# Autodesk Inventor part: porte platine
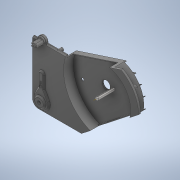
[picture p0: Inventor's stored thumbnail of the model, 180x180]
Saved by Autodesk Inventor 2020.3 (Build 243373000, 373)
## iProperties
Created: 2020-09
Part Number: porte platine
Material: Plastique ABS
Document SubType Name: Modeling
Designer: ficho
Density: 1.06 g/cm^3
Appearance: Lisse - Noir
Mass: 156.331 g
Surface Area: 1026.77 cm^2
Volume: 147.482 cm^3
Author: ficho
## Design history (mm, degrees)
sketch "Esquisse1"
  geometry: L1 (0, 0)-(123, 0); L2 (0, 150)-(0, 0) reference; L3 (123, 0)-(266.132, 112.432); L4 (123, 0)-(298, 0); L5 (81.513, 142)-(222.171, 188.034); L6 (84, 150)-(0, 150) reference; C1 r 3.5 at (178.4, 112); C2 r 3 at (101, 94); C3 r 10 at (160.2, 111.986); A1 r 104.643 centre (182.601, 114.958) between (84, 150) and (145.019, 17.296); A2 r 68 centre (178.4, 112) between (244.316, 95.295) and (192.867, 178.443); A3 r 87.733 centre (178.4, 112) between (266.132, 112.432) and (222.171, 188.034); A4 r 22.5 centre (101, 94) between (84.399, 78.813) and (79.135, 99.308); 1 further point
  constraints: 12 end point, 12 point on circle, 7 centre point, 3 coincident, 3 horizontal, 3 point on line, 1 parallel, 1 vertical
  dimensions: "d3" = 38.15 deg angle of L4 L3; "d6" = 28 distance of A1.end L1.end; "d7" = 78 distance from line of point (78, 112) L2; "d9" = 84 distance from line of L6.start L2; "d10" = 148 distance of L5.end L5.start; "d11" = 161.878 deg angle of L5 L6; "d14" = 30.83438 distance of L5.end A2.end; "d15" = 7 diameter of C1; "d18" = 6 diameter of C2; "d19" = 45 diameter of A4; "d20" = 20 diameter of C3; "d21" = 43 distance edge to line of C3 L5
extrude "Extrusion1" new body sketch "Esquisse1" distance "d23" = 33; taper "d24" = 0 deg
sketch "Esquisse2"
  geometry: L1 (123, 0)-(266.132, 112.432) reference; L2 (222.171, 188.034)-(81.513, 142) reference; A1 r 68 centre (178.4, 112) between (244.316, 95.295) and (192.867, 178.443) reference; A2 r 104.643 centre (182.601, 114.958) between (84, 150) and (145.019, 17.296) reference; 1 further point
extrude "Extrusion2" cut sketch "Esquisse2" distance "d25" = 21; taper "d26" = 0 deg
sketch "Esquisse3"
  geometry: L1 (244.316, 95.295)-(145.019, 17.296) reference; L2 (81.513, 142)-(192.867, 178.443) reference; L3 (142.869, 18.151)-(245.025, 98.395); L4 (244.316, 95.295)-(145.019, 17.296) reference; L5 (80.926, 139.704)-(196.531, 177.538); L6 (81.513, 142)-(192.867, 178.443) reference; C1 r 3 at (101, 94) reference; C2 r 10 at (160.2, 111.986) reference; A1 r 104.643 centre (182.601, 114.958) between (81.513, 142) and (145.019, 17.296) reference; A2 r 68 centre (178.4, 112) between (244.316, 95.295) and (192.867, 178.443) reference; 1 further point
  constraints: 4 end point, 4 point on circle, 2 parallel
  dimensions: "d27" = 2 distance between parallel lines of L1 L3; "d28" = 2 distance between parallel lines of L2 L5 (= d27)
extrude "Extrusion3" cut sketch "Esquisse3" distance "d29" = 4; taper "d30" = 0 deg
extrude "Extrusion4" join sketch "Esquisse1" distance "d31" = 52; taper "d32" = 0 deg
fillet "Congé1" dims "d33" = 3.5
node "Plan de construction1"
  node "Axe de construction1"
sketch "Esquisse5"
  geometry: L1 (28, 73)-(-11.719, 73); L2 (-11.719, 73)-(-11.719, 113.106); L3 (-11.719, 113.106)-(28, 113.106); L4 (28, 113.106)-(28, 73); L5 (33, 44.145)-(33, 87.733) reference; L6 (33, 68)-(8, 68) reference; L7 (-24.463, 0)-(64.744, 0) reference; 1 further point
  constraints: 8 end point, 2 parallel, 1 horizontal, 1 perpendicular
  dimensions: "d36" = 5 distance between parallel lines of L4 L5; "d37" = 5 distance between parallel lines of L1 L6 (= d36)
revolve "Révolution1" sketch "Esquisse5" stored, may be unused: angle "d38" = 180 deg
sketch "Esquisse6"
  geometry: L1 (28, -260.408)-(-21.682, -260.408); L2 (-21.682, -260.408)-(-21.682, -105.427); L3 (-21.682, -105.427)-(28, -105.427); L4 (28, -105.427)-(28, -260.408); L5 (33, -94.212)-(33, -178.211) reference; L6 (33, -100.427)-(8, -100.427) reference; L7 (-36.418, 0)-(66.736, 0) reference; 1 further point
  constraints: 8 end point, 2 parallel, 1 horizontal, 1 perpendicular
  dimensions: "d39" = 5 distance between parallel lines of L4 L5; "d40" = 5 distance between parallel lines of L6 L3 (= d39)
revolve "Révolution2" sketch "Esquisse6" stored, may be unused: angle "d41" = 150 deg
fillet "Congé2" dims "d42" = 15
sketch "Esquisse7"
  geometry: L1 (80.059, 0)-(80.059, -135) reference; L2 (0, 0)-(80.059, 0) reference; L3 (-42.941, -150)-(-60.333, -136.338) reference; L4 (65.059, -150)-(-42.941, -150) reference; L5 (-170.363, -49.909)-(-186.073, -37.568) reference; L6 (-142.112, 38.034)-(-121.41, 31.259) reference; L7 (-183.053, -36.125)-(-170.94, -45.641); L8 (-125.936, 29.583)-(-141.761, 34.763); L9 (65.059, -147)-(-41.903, -147); L10 (-41.903, -147)-(-57.13, -135.039); L11 (1.107, -3)-(77.059, -3); L12 (77.059, -3)-(77.059, -135); A1 r 15 centre (65.059, -135) between (65.059, -150) and (80.059, -135) reference; A2 r 105.427 centre (-98.341, -38) between (-60.333, -136.338) and (0, 0) reference; A3 r 73 centre (-98.341, -38) between (-121.41, 31.259) and (-170.363, -49.909) reference; A4 r 87.733 centre (-98.341, -38) between (-142.112, 38.034) and (-186.073, -37.568) reference; A5 r 84.733 centre (-98.341, -38) between (-141.761, 34.763) and (-183.053, -36.125); A6 r 12 centre (65.059, -135) between (65.059, -147) and (77.059, -135); A7 r 105.427 centre (-98.341, -38) between (-60.333, -136.338) and (0, 0) reference; A8 r 73 centre (-98.341, -38) between (-121.41, 31.259) and (-170.363, -49.909) reference; 1 further point
  constraints: 12 end point, 8 point on circle, 2 centre point, 1 other
  dimensions: "d43" = 3 distance between parallel lines of L5 L7; "d44" = 3 radial gap between concentric circles of A1 A6
extrude "Extrusion5" cut sketch "Esquisse7" distance "d45" = 3; taper "d46" = 0 deg
sketch "Esquisse8"
  geometry: L1 (-84, 150)-(-80.059, 150) reference; L2 (-201.47, 181.259)-(-81.513, 142) reference; L3 (-140.393, 13.662)-(-250.422, 100.091) reference; L4 (-81.513, 142)-(-76.895, 140.489); L5 (-84, 150)-(-80.059, 150) reference; C1 r 10 at (-160.2, 111.986) reference; C2 r 3 at (-101, 94) reference; A1 r 105.427 centre (-178.4, 112) between (-140.393, 13.662) and (-80.059, 150) reference; A2 r 104.643 centre (-182.601, 114.958) between (-81.513, 142) and (-84, 150) reference; A3 r 73 centre (-178.4, 112) between (-201.47, 181.259) and (-250.422, 100.091) reference; A4 r 104.643 centre (-182.601, 114.958) between (-80.926, 139.704) and (-81.513, 142) reference; A5 r 105.427 centre (-178.4, 112) between (-140.393, 13.662) and (-80.059, 150) reference; A6 r 104.643 centre (-182.601, 114.958) between (-145.019, 17.296) and (-84, 150) reference; 2 further points
  constraints: 2 end point, 1 point on circle
extrude "Extrusion6" cut sketch "Esquisse8" stored distance "d47" = 10; taper "d48" = 0 deg
sketch "Esquisse9"
  geometry: L1 (-201.47, 181.259)-(-76.895, 140.489) reference; L2 (-140.393, 13.662)-(-250.422, 100.091) reference; L3 (-203.033, 180.718)-(-187.21, 175.54); L4 (-186.221, 175.244)-(-76.561, 139.273); L5 (-139.329, 14.08)-(-236.917, 90.736); L6 (-237.702, 91.371)-(-250.647, 101.539); L7 (-213.165, 132.272)-(-241.256, 149.124); L8 (-212.651, 133.13)-(-240.741, 149.981); L9 (-245.025, 98.395)-(-142.869, 18.151) reference; L10 (-119.045, 24.869)-(-226.02, 108.899); L11 (-226.813, 109.522)-(-249.73, 127.524); L12 (-236.917, 90.736)-(-226.02, 108.899); L13 (-118.182, 25.463)-(-225.502, 109.764); L14 (-226.295, 110.386)-(-249.487, 128.604); L15 (-237.702, 91.371)-(-226.813, 109.522); L16 (-226.295, 110.386)-(-213.165, 132.272); L17 (-226.96, 166.506)-(-198.274, 157.096); L18 (-197.299, 156.776)-(-73.049, 116.02); L19 (-225.502, 109.764)-(-197.299, 156.776); L20 (-196.772, 157.656)-(-186.221, 175.244); L21 (-212.651, 133.13)-(-198.274, 157.096); L22 (-197.746, 157.976)-(-187.21, 175.54); L23 (-226.087, 167.272)-(-197.746, 157.976); L24 (-196.772, 157.656)-(-73.096, 117.087); C1 r 3 at (-101, 94) reference; C2 r 10 at (-160.2, 111.986) reference; C3 r 3.5 at (-178.4, 112) reference; A1 r 73 centre (-178.4, 112) between (-201.47, 181.259) and (-250.422, 100.091) reference; A2 r 105.427 centre (-178.4, 112) between (-140.393, 13.662) and (-76.895, 140.489) reference; 8 further points
  constraints: 42 end point, 25 parallel, 8 point on circle, 7 other
extrude "Extrusion7" cut sketch "Esquisse9" distance "d59" = 5; taper "d60" = 0 deg
sketch "Esquisse10"
  geometry: L1 (80.059, 0)-(80.059, -135) reference; L2 (65.059, -150)-(-42.941, -150) reference; C1 r 6 at (55.059, -127.5); 1 further point
  constraints: 1 centre point
  dimensions: "d61" = 25 distance from line of C1.centre L1; "d62" = 22.5 distance from line of L2 C1.centre; "d63" = 12 diameter of C1
extrude "Extrusion8" join sketch "Esquisse10" distance "d64" = 16; taper "d65" = 0 deg
sketch "Esquisse11"
  geometry: C1 r 6 at (0, 0) reference; 2 further points
  constraints: 1 coincident
hole "Perçage1" sketch "Esquisse11" at (0, 0) diameter "d66" = 8; stored, may be unused: countersink angle "d70" = 90 deg, drill point angle "d72" = 118 deg; dims "d67" = 6, "d68" = 4, "d69" = 2, "d71" = 8
sketch "Esquisse12"
  geometry: C1 r 4 at (25, 22.5) reference; C2 r 13.5 at (25, 22.5); 1 further point
  constraints: 1 centre point, 1 coincident
  dimensions: "d73" = 27 diameter of C2
extrude "Extrusion9" join sketch "Esquisse12" distance "d74" = 8.5; taper "d75" = 0 deg
sketch "Esquisse13" dims "d76" = 40, "d79" = 15
  geometry: L1 (15, 0)-(123, 0) reference; L2 (32.395, 81.5)-(17.395, 81.5); L3 (17.395, 81.5)-(17.395, 50.391); L4 (32.395, 50.706)-(32.395, 81.5); L5 (25, 22.5)-(25, 55.638); C1 r 13.5 at (25, 22.5) reference; A1 r 120.352 centre (117.494, -16.426) between (17.395, 50.391) and (6.566, 30.258); A2 r 120.352 centre (-67.494, -16.426) between (43.434, 30.258) and (32.395, 50.706); 5 further points
  constraints: 8 end point, 5 point on circle, 3 symmetric about line, 2 centre point, 1 coincident, 1 horizontal, 1 parallel, 1 perpendicular, 1 vertical, 8 other
  dimensions: "d80" = 89 dimension on L1
extrude "Extrusion10" join sketch "Esquisse13" distance "d81" = 4; taper "d82" = 0 deg
chamfer "Chanfrein1" distance "d83" = 3; stored, may be unused: second distance "d84" = 2, angle "d85" = 50 deg
chamfer "Chanfrein2" distance "d86" = 3; stored, may be unused: second distance "d87" = 2, angle "d88" = 50 deg
sketch "Esquisse14"
  geometry: C1 r 3 at (25, 55.5); C2 r 4 at (25, 22.5) reference; 1 further point
  constraints: 1 centre point
  dimensions: "d89" = 6 diameter of C1; "d90" = 26 dimension on C2 C1
extrude "Extrusion11" cut sketch "Esquisse14" extent not by distance; stored distance "d91" = 15; taper "d92" = 0 deg
sketch "Esquisse15"
  geometry: L1 (25, 59.5)-(23.75, 59.5); L2 (23.75, 59.5)-(23.75, 67); L3 (23.75, 67)-(25, 67); L4 (25, 67)-(25, 59.5); L5 (25, 59.5)-(26.25, 59.5); L6 (26.25, 59.5)-(26.25, 67); L7 (26.25, 67)-(25, 67); L8 (25, 67)-(25, 59.5); C1 r 3 at (25, 55.5) reference; C2 r 4 at (25, 55.5); 2 further points
  constraints: 16 end point, 4 parallel, 2 horizontal, 2 perpendicular, 1 centre point, 1 tangent
  dimensions: "d93" = 1 radial gap between concentric circles of C1 C2; "d94" = 1.25 distance of L2.end L3.end; "d95" = 7.5 distance of L1.end L2.end; "d97" = 1.25 distance of L7.end L6.end
extrude "Extrusion12" cut sketch "Esquisse15" extent not by distance; stored distance "d98" = 15; taper "d99" = 0 deg
sketch "Esquisse16"
  geometry: L1 (0, 150)-(0, 15) reference; L2 (84, 150)-(0, 150) reference; L3 (34, 153)-(34, 150); L4 (14, 153)-(14, 150); A1 r 10 centre (24, 153) between (34, 153) and (14, 153); 1 further point
  constraints: 4 end point, 2 perpendicular, 2 point on circle, 2 point on line, 2 tangent, 1 centre point
  dimensions: "d100" = 20 diameter of A1; "d101" = 24 distance from line of L1 A1.centre; "d102" = 13 dimension on A1 L2
extrude "Extrusion13" join sketch "Esquisse16" stored distance "d103" = 3; taper "d104" = 0 deg
sketch "Esquisse17"
  geometry: C1 r 9 at (24, 153); A1 r 10 centre (24, 153) between (34, 153) and (14, 153) reference; 1 further point
  constraints: 1 centre point, 1 coincident
  dimensions: "d105" = 18 diameter of C1
extrude "Extrusion14" join sketch "Esquisse17" distance "d106" = 3; taper "d107" = 0 deg
chamfer "Chanfrein3" distance "d108" = 3; stored, may be unused: second distance "d109" = 2, angle "d110" = 15 deg
sketch "Esquisse18"
  geometry: L1 (3.25, 4)-(-4.25, 4); L2 (-4.25, 4)-(-4.25, -4); L3 (-4.25, -4)-(3.25, -4); C1 r 8.196 at (0, 0) reference; A1 r 4 centre (3.25, 0) between (3.25, -4) and (3.25, 4); 1 further point
  constraints: 6 end point, 2 point on circle, 1 centre point, 1 horizontal, 1 parallel, 1 perpendicular, 1 tangent
  dimensions: "d111" = 8 distance between parallel lines of L3 L1; "d112" = 4 distance from line of C1.centre L1 (= 0.5 x d111); "d114" = 11.5 dimension on A1 L2
extrude "Extrusion15" join sketch "Esquisse18" distance "d115" = 17; taper "d116" = 0 deg
sketch "Esquisse19"
  geometry: L1 (-4.25, 4)-(-4.25, -4) reference; L2 (-4.25, 1.5)-(1.75, 1.5); L3 (1.75, 1.5)-(1.75, -1.5); L4 (1.75, -1.5)-(-4.25, -1.5); L5 (-4.25, -1.5)-(-4.25, 1.5); 2 further points
  constraints: 8 end point, 2 parallel, 1 horizontal, 1 perpendicular, 1 point on line
  dimensions: "d117" = 3 distance between parallel lines of L4 L2; "d118" = 6 distance between parallel lines of L1 L3; "d119" = 2.5 distance from line of L2 L1.start; "d120" = 2.5 distance of L4.end L1.end (derived)
extrude "Extrusion16" cut sketch "Esquisse19" extent not by distance; stored distance "d121" = 0; taper "d122" = 0 deg
sketch "Esquisse20"
  geometry: L1 (103.25, 157)-(103.25, 154.5) reference; L2 (103.25, 151.5)-(103.25, 149) reference; L3 (103.25, 157)-(100.25, 157); L4 (100.25, 157)-(100.25, 149); L5 (100.25, 149)-(103.25, 149); L6 (103.25, 149)-(103.25, 157); L7 (100.25, 155)-(93, 155); L8 (93, 155)-(93, 151); L9 (93, 151)-(100.25, 151); L10 (100.25, 151)-(100.25, 155); L11 (103.25, 151.5)-(97.25, 151.5) reference; A1 r 10 centre (99, 153) between (109, 153) and (89, 153) reference; 5 further points
  constraints: 16 end point, 4 parallel, 2 horizontal, 2 perpendicular, 1 point on line
  dimensions: "d123" = 3 distance of L5.end L4.end; "d124" = 4 distance between parallel lines of L9 L7; "d125" = 0.5 distance between parallel lines of L9 L11; "d126" = 4 distance edge to line of A1 L8
extrude "Extrusion17" cut sketch "Esquisse20" distance "d127" = 12; taper "d128" = 0 deg
sketch "Esquisse21"
  geometry: L1 (103.25, 157)-(103.25, 154.5) reference; L2 (100.25, 155)-(100.25, 157) reference; L3 (103.25, 157)-(100.25, 157); L4 (100.25, 157)-(100.25, 156.5); L5 (100.25, 156.5)-(103.25, 156.5); L6 (103.25, 156.5)-(103.25, 157); 3 further points
  constraints: 8 end point, 2 parallel, 1 horizontal, 1 perpendicular, 1 point on line
  dimensions: "d129" = 0.5 distance of L4.end L3.end
extrude "Extrusion18" join sketch "Esquisse21" stored distance "d130" = 10; taper "d131" = 0 deg
sketch "Esquisse22"
  geometry: L1 (-4.25, -4)-(-1.25, -4) reference; L2 (1.75, -1.5)-(-4.25, -1.5) reference; L3 (-4.25, -4)-(-1.75, -4); L4 (-1.75, -4)-(-1.75, -1.5); L5 (-1.75, -1.5)-(-4.25, -1.5); L6 (-4.25, -1.5)-(-4.25, -4); L7 (-4.25, 4)-(3.25, 4) reference; L8 (-4.25, 1.5)-(1.75, 1.5) reference; L9 (-4.25, 4)-(-1.75, 4); L10 (-1.75, 4)-(-1.75, 1.5); L11 (-1.75, 1.5)-(-4.25, 1.5); L12 (-4.25, 1.5)-(-4.25, 4); L13 (4.75, 1.5)-(6.958, 1.5); L14 (6.958, -1.5)-(4.75, -1.5); L15 (4.75, -1.5)-(4.75, 1.5); L16 (1.75, -1.5)-(-4.25, -1.5) reference; A1 r 4 centre (3.25, 0) between (3.25, -4) and (3.25, 4) reference; 5 further points
  constraints: 22 end point, 5 parallel, 3 horizontal, 3 point on line, 2 perpendicular, 2 point on circle, 1 collinear
  dimensions: "d132" = 2.5 distance of L5.end L4.end; "d133" = 3 distance between parallel lines of L14 L13; "d134" = 2.5 distance edge to line of A1 L15
extrude "Extrusion19" join sketch "Esquisse22" distance "d135" = 2; taper "d136" = 0 deg
chamfer "Chanfrein4" distance "d137" = 3; stored, may be unused: second distance "d138" = 2, angle "d139" = 15 deg
sketch "Esquisse23"
  geometry: L1 (60.087, -101.804)-(60.087, -127.5) reference; L2 (63.096, -116.971)-(60.087, -116.971); L3 (60.087, -116.971)-(60.087, -114.971); L4 (60.087, -114.971)-(63.096, -114.971); L5 (65.096, -114.971)-(65.096, -116.971); L6 (65.096, -118.471)-(63.096, -118.471); L7 (63.096, -113.971)-(65.096, -113.971); L8 (65.096, -113.971)-(65.096, -118.471); L9 (63.096, -118.471)-(63.096, -116.971); L10 (63.096, -114.971)-(63.096, -113.971); A1 r 13.5 centre (55.059, -127.5) between (60.087, -114.971) and (65.096, -118.471) reference; 4 further points
  constraints: 18 end point, 5 parallel, 3 perpendicular, 2 horizontal, 2 point on circle, 2 point on line
  dimensions: "d140" = 2 distance between parallel lines of L2 L4; "d142" = 1 distance between parallel lines of L7 L4; "d143" = 1.5 distance between parallel lines of L2 L6
  node "Référence1"
node "Plan de construction2"
extrude "Extrusion20" join sketch "Esquisse23" stored distance "d144" = 10; taper "d145" = 0 deg
sketch "Esquisse25"
  geometry: C1 r 4 at (-28.676, -136.868) reference; C2 r 4 at (19.198, -4.572) reference; C3 r 4 at (-165.371, 7.31) reference; 1 further point
  node "Référence2"
  node "Référence3"
  node "Référence4"
node "Plan de construction3"
extrude "Extrusion21" join sketch "Esquisse25" stored distance "d146" = 10; taper "d147" = 0 deg
sketch "Esquisse26"
  geometry: C1 r 3 at (-101, 94) reference; C2 r 20 at (-101, 94); 1 further point
  constraints: 1 centre point, 1 coincident
  dimensions: "d148" = 40 diameter of C2
extrude "Extrusion22" cut sketch "Esquisse26" distance "d149" = 2; taper "d150" = 0 deg
node "Solide1"
node "Boucle projetée1"
node "Boucle projetée2"
node "Boucle projetée3"
node "Boucle projetée4"
node "Boucle projetée5"
other parameters: "d1" = 123, "d4" = 8, "d5" = 28.25304, "d8" = 38, "d13" = 136, "d49" = 1, "d52" = 1, "d57" = 1, "d58" = 1, "d141" = 2
